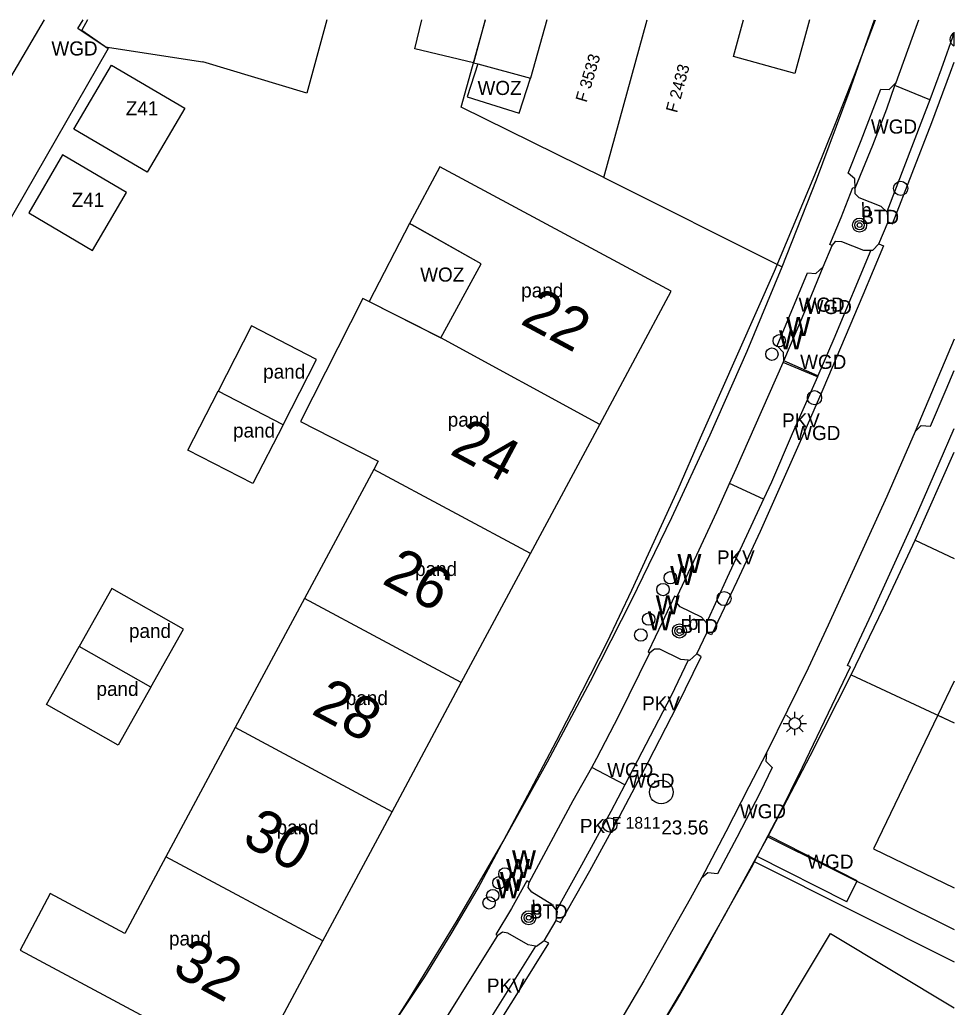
# Model space of a CAD drawing. Extents: x 198240 to 198429, y 356553 to 356721.
# Drawn here: x 198389.56 to 198429.25, y 356678.7 to 356720.63 of the extents above; entities that cross this region are included whole.
import ezdxf

# ---------------------------------------------------------------- set-up
doc = ezdxf.new("R2010")
doc.units = 0
for name, color, linetype in [('begroeid terreindeel kenmerkpunt', 7, 'Continuous'), ('bijgebouw', 7, 'Continuous'), ('BOOM', 7, 'Continuous'), ('grens individueel parkeervak', 7, 'Continuous'), ('Grens maaiveld', 7, 'Continuous'), ('grens WOZ object', 7, 'Continuous'), ('hoofdgebouw', 7, 'Continuous'), ('Hoogtepunt', 7, 'Continuous'), ('huisnummerreeks BGT', 7, 'Continuous'), ('identificerend kenmerkpunt bijpand', 7, 'Continuous'), ('identificerend kenmerkpunt pand', 7, 'Continuous'), ('identificerend kenmerkpunt parkeervak', 7, 'Continuous'), ('identificerend kenmerkpunt WOZ object', 7, 'Continuous'), ('Inspectieput_rioolput', 7, 'Continuous'), ('kant verharding', 7, 'Continuous'), ('kolk', 7, 'Continuous'), ('LICHTMAST', 7, 'Continuous'), ('Perceelnummer', 7, 'Continuous'), ('perceelsgrens_definitief', 7, 'Continuous'), ('tussenmuur', 7, 'Continuous'), ('tussenmuur bijgebouw (GBKN Zuid)', 7, 'Continuous'), ('vlakafsluiter', 7, 'Continuous'), ('waterleidingput', 7, 'Continuous'), ('wegdeel kenmerkpunt', 7, 'Continuous'), ('weginrichtingselement', 7, 'Continuous'), ('weginrichtingselement lijn', 7, 'Continuous')]:
    doc.layers.add(name, color=color, linetype=linetype)

msp = doc.modelspace()

# ---------------------------------------------------------------- linework, layer by layer
at = {"layer": 'bijgebouw'}
for p, q in [((198409.332, 356720.628), (198408.829, 356718.798)), ((198411.94, 356720.628), (198411.258, 356718.147)), ((198391.86, 356715.984), (198393.452, 356718.699)), ((198393.452, 356718.699), (198396.568, 356716.873)), ((198408.829, 356718.798), (198409.018, 356718.752)), ((198409.018, 356718.752), (198411.258, 356718.147)), ((198396.568, 356716.873), (198394.976, 356714.157)), ((198394.976, 356714.157), (198391.86, 356715.984)), ((198391.38, 356714.887), (198389.939, 356712.431)), ((198394.095, 356713.293), (198391.38, 356714.887)), ((198392.654, 356710.838), (198394.095, 356713.293)), ((198389.939, 356712.431), (198392.654, 356710.838))]:
    msp.add_line(p, q, dxfattribs=at)
for points in [[(198408.829, 356718.798), (198406.343, 356719.398), (198406.64, 356720.628)], [(198400.743, 356703.434), (198402.167, 356706.208), (198399.405, 356707.627), (198397.981, 356704.853)], [(198400.743, 356703.434), (198399.459, 356700.933), (198396.697, 356702.352), (198397.981, 356704.853)], [(198395.132, 356692.295), (198396.519, 356694.756), (198393.475, 356696.473), (198392.088, 356694.012)], [(198395.132, 356692.295), (198393.745, 356689.834), (198390.701, 356691.551), (198392.088, 356694.012)]]:
    msp.add_lwpolyline(points, dxfattribs=at)
at = {"layer": 'BOOM'}
for centre, radius in [((198425.228, 356711.909), 0.3), ((198425.228, 356711.909), 0.2), ((198425.228, 356711.909), 0.1), ((198417.58, 356694.677), 0.3), ((198417.58, 356694.677), 0.2), ((198417.58, 356694.677), 0.1), ((198411.177, 356682.499), 0.3), ((198411.177, 356682.499), 0.2), ((198411.177, 356682.499), 0.1)]:
    msp.add_circle(centre, radius, dxfattribs=at)
at = {"layer": 'grens individueel parkeervak'}
for p, q in [((198428.208, 356717.232), (198426.732, 356717.831)), ((198423.437, 356705.468), (198421.981, 356706.082)), ((198421.145, 356700.266), (198419.706, 356700.935)), ((198415.259, 356688.142), (198413.851, 356688.883))]:
    msp.add_line(p, q, dxfattribs=at)
at = {"layer": 'Grens maaiveld'}
for q in [(198422.01, 356706.149), (198423.437, 356705.468)]:
    msp.add_line((198423.457, 356705.515), q, dxfattribs=at)
for points in [[(198392.443, 356720.628), (198392.198, 356720.187), (198393.31, 356719.404), (198387.535, 356709.369)], [(198426.437, 356712.046), (198426.632, 356711.964), (198428.296, 356716.263), (198429.097, 356718.399), (198429.251, 356718.83)], [(198426.047, 356711.12), (198426.247, 356711.034), (198425.369, 356708.932), (198423.667, 356704.924), (198422.764, 356702.853), (198421.004, 356698.906), (198420.01, 356696.778), (198418.935, 356694.513), (198418.738, 356694.603)], [(198425.712, 356710.842), (198424.13, 356707.084), (198423.457, 356705.515)], [(198412.347, 356682.39), (198412.533, 356682.299), (198413.769, 356684.494), (198415.038, 356686.8), (198416.25, 356689.104), (198417.492, 356691.528), (198418.504, 356693.583), (198418.315, 356693.702)], [(198404.916, 356670.796), (198405.102, 356670.682), (198406.526, 356672.803), (198407.964, 356674.984), (198409.355, 356677.141), (198410.82, 356679.462), (198412.025, 356681.421), (198411.835, 356681.521)]]:
    msp.add_lwpolyline(points, dxfattribs=at)
at = {"layer": 'grens WOZ object'}
for p, q in [((198409.018, 356718.752), (198408.557, 356717.35)), ((198410.766, 356716.663), (198411.258, 356718.147)), ((198408.557, 356717.35), (198410.766, 356716.663)), ((198406.116, 356711.982), (198404.4, 356708.67)), ((198409.159, 356710.26), (198406.116, 356711.982)), ((198407.45, 356707.121), (198409.159, 356710.26)), ((198404.4, 356708.67), (198407.45, 356707.121))]:
    msp.add_line(p, q, dxfattribs=at)
at = {"layer": 'hoofdgebouw'}
for p, q in [((198411.253, 356697.967), (198414.193, 356703.45)), ((198404.786, 356701.891), (198404.596, 356701.537)), ((198404.596, 356701.537), (198401.654, 356696.054)), ((198408.312, 356692.484), (198411.253, 356697.967)), ((198401.654, 356696.054), (198398.712, 356690.572)), ((198429.251, 356692.542), (198428.554, 356691.097)), ((198405.372, 356687.001), (198408.312, 356692.484)), ((198398.712, 356690.572), (198395.77, 356685.089)), ((198402.431, 356681.517), (198405.372, 356687.001))]:
    msp.add_line(p, q, dxfattribs=at)
for points in [[(198423.102, 356720.628), (198422.485, 356718.353), (198419.869, 356719.062), (198420.294, 356720.628)], [(198414.193, 356703.45), (198417.228, 356709.109), (198407.402, 356714.379), (198406.116, 356711.982), (198406.233, 356711.919)], [(198407.45, 356707.121), (198409.159, 356710.26), (198406.233, 356711.919)], [(198407.45, 356707.121), (198404.136, 356708.789), (198401.488, 356703.564), (198404.786, 356701.891)], [(198428.554, 356691.097), (198425.817, 356685.422), (198429.251, 356683.766)], [(198395.77, 356685.089), (198394.02, 356681.827), (198390.856, 356683.525), (198389.57, 356681.128), (198399.396, 356675.858), (198402.431, 356681.517)], [(198420.705, 356676.348), (198423.998, 356681.827), (198429.251, 356678.669)]]:
    msp.add_lwpolyline(points, dxfattribs=at)
at = {"layer": 'Inspectieput_rioolput'}
msp.add_circle((198416.807, 356687.836), 0.5, dxfattribs=at)
at = {"layer": 'kant verharding'}
for p, q in [((198426.732, 356717.831), (198426.78, 356717.968)), ((198426.047, 356711.12), (198426.437, 356712.046)), ((198423.689, 356710.141), (198424.064, 356711.049)), ((198421.981, 356706.082), (198422.01, 356706.149)), ((198418.315, 356693.702), (198418.738, 356694.603)), ((198420.885, 356685.099), (198421.345, 356685.987)), ((198425.133, 356684.071), (198421.345, 356685.987)), ((198424.682, 356683.178), (198420.885, 356685.099)), ((198411.835, 356681.521), (198412.347, 356682.39))]:
    msp.add_line(p, q, dxfattribs=at)
for points in [[(198390.591, 356720.628), (198384.945, 356711.036)], [(198404.586, 356676.725), (198406.76, 356679.993), (198407.876, 356681.813), (198409.023, 356683.755), (198411.249, 356687.914), (198412.354, 356690.009), (198413.448, 356692.124), (198414.512, 356694.208), (198415.559, 356696.412), (198417.527, 356700.704), (198418.469, 356702.874), (198419.338, 356704.811), (198421.62, 356709.947), (198423.335, 356714.04), (198424.205, 356716.22), (198425.011, 356718.278), (198425.903, 356720.628)], [(198426.78, 356717.968), (198427.469, 356719.845), (198427.749, 356720.628)], [(198429.251, 356720.08), (198428.694, 356718.534), (198428.208, 356717.232)], [(198425.048, 356713.475), (198425.033, 356713.869), (198424.748, 356714.11), (198425.303, 356715.506), (198426.134, 356717.681), (198426.493, 356717.668), (198426.78, 356717.968)], [(198425.048, 356713.475), (198425.794, 356715.305), (198426.385, 356716.847), (198426.732, 356717.831)], [(198428.208, 356717.232), (198427.908, 356716.427), (198426.384, 356712.478)], [(198424.064, 356711.049), (198423.971, 356711.092), (198424.451, 356712.233), (198424.95, 356713.5), (198425.048, 356713.475)], [(198426.384, 356712.478), (198426.145, 356712.704), (198425.212, 356713.065), (198425.049, 356713.233), (198425.048, 356713.475)], [(198426.437, 356712.046), (198426.418, 356712.446), (198426.384, 356712.478)], [(198424.064, 356711.049), (198424.222, 356711.233), (198424.457, 356711.211), (198425.39, 356710.843), (198425.712, 356710.842)], [(198425.712, 356710.842), (198425.794, 356710.842), (198426.047, 356711.12)], [(198422.01, 356706.149), (198421.994, 356706.497), (198421.733, 356706.789), (198423.019, 356709.885), (198423.378, 356709.856), (198423.689, 356710.141)], [(198422.01, 356706.149), (198422.948, 356708.347), (198423.689, 356710.141)], [(198429.251, 356707.07), (198429.249, 356707.065), (198427.592, 356703.146)], [(198419.706, 356700.935), (198419.99, 356701.56), (198420.801, 356703.387), (198421.981, 356706.082)], [(198427.592, 356703.146), (198427.847, 356703.4), (198428.243, 356703.379), (198428.907, 356704.926), (198429.251, 356705.743)], [(198423.437, 356705.468), (198422.371, 356703.044), (198421.482, 356700.991), (198421.145, 356700.266)], [(198427.592, 356703.146), (198426.387, 356700.387), (198423.895, 356694.926), (198423.04, 356693.104), (198422.168, 356691.314), (198421.275, 356689.505)], [(198421.345, 356685.987), (198421.795, 356686.857), (198422.801, 356688.9), (198424.843, 356693.153), (198424.72, 356693.21), (198425.736, 356695.385), (198427.642, 356699.599), (198428.615, 356701.808), (198429.251, 356703.276)], [(198417.468, 356696.106), (198418.319, 356697.915), (198419.162, 356699.737), (198419.706, 356700.935)], [(198421.145, 356700.266), (198419.606, 356696.952), (198418.721, 356695.028)], [(198417.468, 356696.106), (198417.372, 356696.154), (198416.851, 356695.032), (198416.243, 356693.797), (198416.322, 356693.749)], [(198418.721, 356695.028), (198418.512, 356695.267), (198417.612, 356695.703), (198417.449, 356695.882), (198417.468, 356696.106)], [(198418.738, 356694.603), (198418.773, 356694.968), (198418.721, 356695.028)], [(198413.851, 356688.883), (198414.071, 356689.274), (198414.998, 356691.068), (198416.322, 356693.749)], [(198417.942, 356693.434), (198417.642, 356693.462), (198416.745, 356693.898), (198416.523, 356693.91), (198416.322, 356693.749)], [(198417.942, 356693.434), (198417.232, 356691.92), (198415.259, 356688.142)], [(198418.315, 356693.702), (198418.002, 356693.428), (198417.942, 356693.434)], [(198421.275, 356689.505), (198421.252, 356689.147), (198421.52, 356688.882), (198421.009, 356687.825), (198420.023, 356685.909), (198419.188, 356684.359), (198418.788, 356684.405), (198418.513, 356684.184)], [(198421.275, 356689.505), (198420.528, 356688.062), (198419.549, 356686.142), (198418.513, 356684.184)], [(198411.191, 356683.991), (198413.062, 356687.483), (198413.851, 356688.883)], [(198415.259, 356688.142), (198414.67, 356687.011), (198413.423, 356684.735), (198412.352, 356682.826)], [(198393.74, 356645.683), (198394.852, 356647.053), (198396.077, 356648.617), (198397.345, 356650.191), (198399.817, 356653.369), (198401.05, 356654.94), (198403.957, 356658.838), (198407.667, 356663.939), (198410.624, 356668.271), (198412.002, 356670.335), (198414.253, 356673.784), (198415.317, 356675.477), (198416.394, 356677.211), (198417.49, 356679.043), (198418.49, 356680.762), (198419.487, 356682.592), (198420.694, 356684.729), (198420.885, 356685.099)], [(198418.513, 356684.184), (198418.032, 356683.303), (198416.065, 356679.815), (198415.042, 356678.098), (198413.982, 356676.397), (198412.924, 356674.725), (198411.836, 356673.035), (198410.73, 356671.365), (198409.617, 356669.703)], [(198411.191, 356683.991), (198411.102, 356684.062), (198410.446, 356682.888), (198409.778, 356681.793), (198409.862, 356681.744)], [(198412.352, 356682.826), (198412.165, 356683.067), (198411.302, 356683.587), (198411.157, 356683.784), (198411.191, 356683.991)], [(198412.347, 356682.39), (198412.402, 356682.762), (198412.352, 356682.826)], [(198406.901, 356677.03), (198407.203, 356677.485), (198409.346, 356680.906), (198409.862, 356681.744)], [(198411.465, 356681.29), (198411.159, 356681.348), (198410.29, 356681.85), (198410.056, 356681.895), (198409.862, 356681.744)], [(198411.465, 356681.29), (198408.989, 356677.334), (198408.215, 356676.157)], [(198411.835, 356681.521), (198411.512, 356681.281), (198411.465, 356681.29)]]:
    msp.add_lwpolyline(points, dxfattribs=at)
at = {"layer": 'kolk'}
msp.add_line((198429.251, 356719.514), (198429.251, 356720.07), dxfattribs=at)
for centre in [(198426.977, 356713.469), (198423.315, 356704.58), (198419.474, 356696.053), (198414.625, 356686.439)]:
    msp.add_circle(centre, 0.3, dxfattribs=at)
msp.add_arc((198429.365, 356719.792), 0.3, 112.3125, 247.6875, dxfattribs=at)
at = {"layer": 'LICHTMAST'}
for p, q in [((198422.482, 356690.998), (198422.482, 356691.248)), ((198422.305, 356690.925), (198422.128, 356691.102)), ((198422.659, 356690.925), (198422.836, 356691.102)), ((198421.982, 356690.748), (198422.232, 356690.748)), ((198422.128, 356690.394), (198422.305, 356690.571)), ((198422.482, 356690.248), (198422.482, 356690.498)), ((198422.836, 356690.394), (198422.659, 356690.571)), ((198422.732, 356690.748), (198422.982, 356690.748))]:
    msp.add_line(p, q, dxfattribs=at)
msp.add_circle((198422.482, 356690.748), 0.25, dxfattribs=at)
at = {"layer": 'perceelsgrens_definitief'}
for points in [[(198392.026, 356720.255), (198392.248, 356720.628)], [(198402.603, 356720.628), (198401.758, 356717.506), (198397.339, 356718.835)], [(198414.372, 356713.928), (198408.309, 356716.912), (198409.334, 356720.628)], [(198414.372, 356713.928), (198416.203, 356720.628)], [(198421.942, 356710.139), (198423.4, 356713.831), (198424.785, 356717.551), (198425.864, 356720.628)], [(198393.187, 356719.473), (198392.026, 356720.255)], [(198393.187, 356719.473), (198397.339, 356718.835)], [(198414.372, 356713.928), (198421.942, 356710.139)], [(198392.722, 356660.05), (198395.103, 356663.112), (198397.425, 356666.219), (198399.689, 356669.369), (198401.891, 356672.562), (198404.033, 356675.796), (198406.114, 356679.07), (198408.131, 356682.383), (198410.086, 356685.733), (198411.977, 356689.12), (198413.803, 356692.543), (198415.563, 356695.999), (198417.258, 356699.488), (198418.887, 356703.008), (198420.448, 356706.559), (198421.942, 356710.139)], [(198427.584, 356698.531), (198429.251, 356702.262)], [(198424.868, 356692.818), (198426.247, 356695.665), (198427.584, 356698.531)], [(198427.584, 356698.531), (198429.251, 356697.749)], [(198421.33, 356685.94), (198421.343, 356685.963), (198423.135, 356689.375), (198424.868, 356692.818)], [(198424.868, 356692.818), (198429.251, 356690.772)], [(198420.752, 356684.884), (198421.33, 356685.94)], [(198421.33, 356685.94), (198429.251, 356682)], [(198415.612, 356675.921), (198417.581, 356679.235), (198419.491, 356682.582), (198420.752, 356684.884)], [(198420.752, 356684.884), (198429.251, 356680.633)]]:
    msp.add_lwpolyline(points, dxfattribs=at)
at = {"layer": 'tussenmuur'}
for p, q in [((198414.193, 356703.45), (198407.45, 356707.121)), ((198411.253, 356697.967), (198404.596, 356701.537)), ((198408.312, 356692.484), (198401.654, 356696.054)), ((198428.554, 356691.097), (198429.251, 356690.77)), ((198405.372, 356687.001), (198398.712, 356690.572)), ((198402.431, 356681.517), (198395.77, 356685.089))]:
    msp.add_line(p, q, dxfattribs=at)
at = {"layer": 'tussenmuur bijgebouw (GBKN Zuid)'}
for p, q in [((198400.743, 356703.434), (198397.981, 356704.853)), ((198395.132, 356692.295), (198392.088, 356694.012))]:
    msp.add_line(p, q, dxfattribs=at)
at = {"layer": 'vlakafsluiter'}
msp.add_line((198424.682, 356683.178), (198425.133, 356684.071), dxfattribs=at)
at = {"layer": 'waterleidingput'}
for centre in [(198421.816, 356707), (198421.816, 356707), (198421.508, 356706.43), (198421.508, 356706.43), (198417.19, 356696.936), (198417.19, 356696.936), (198416.881, 356696.436), (198416.881, 356696.436), (198416.271, 356695.18), (198416.271, 356695.18), (198415.938, 356694.504), (198415.938, 356694.504), (198410.164, 356684.357), (198410.164, 356684.357), (198409.913, 356683.985), (198409.913, 356683.985), (198409.649, 356683.443), (198409.649, 356683.443), (198409.493, 356683.132), (198409.493, 356683.132)]:
    msp.add_circle(centre, 0.263, dxfattribs=at)
at = {"layer": 'weginrichtingselement lijn'}
for points in [[(198426.437, 356712.046), (198426.632, 356711.964), (198428.296, 356716.263), (198429.097, 356718.399), (198429.251, 356718.83)], [(198426.047, 356711.12), (198426.247, 356711.034), (198425.369, 356708.932), (198423.667, 356704.924), (198422.764, 356702.853), (198421.004, 356698.906), (198420.01, 356696.778), (198418.935, 356694.513), (198418.738, 356694.603)], [(198412.347, 356682.39), (198412.533, 356682.299), (198413.769, 356684.494), (198415.038, 356686.8), (198416.25, 356689.104), (198417.492, 356691.528), (198418.504, 356693.583), (198418.315, 356693.702)], [(198404.916, 356670.796), (198405.102, 356670.682), (198406.526, 356672.803), (198407.964, 356674.984), (198409.355, 356677.141), (198410.82, 356679.462), (198412.025, 356681.421), (198411.835, 356681.521)]]:
    msp.add_lwpolyline(points, dxfattribs=at)

# ---------------------------------------------------------------- texts
at = {"layer": 'begroeid terreindeel kenmerkpunt'}
for p in [(198425.303, 356711.958), (198417.619, 356694.585), (198411.223, 356682.468)]:
    msp.add_text('BTD', height=0.6, dxfattribs=at).set_placement(p)
at = {"layer": 'Hoogtepunt'}
msp.add_text('23.56', height=0.6, dxfattribs=at).set_placement((198416.807, 356686.036))
msp.add_text('23.56', height=0.6, dxfattribs=at).set_placement((198416.807, 356686.036))
at = {"layer": 'huisnummerreeks BGT'}
for s, p in [('22', (198410.772, 356707.742)), ('24', (198407.772, 356702.211)), ('26', (198404.892, 356696.715)), ('28', (198401.891, 356691.182)), ('30', (198398.938, 356685.663)), ('32', (198395.971, 356680.143))]:
    msp.add_text(s, height=1.8, rotation=331.8, dxfattribs=at).set_placement(p)
at = {"layer": 'identificerend kenmerkpunt bijpand'}
for s, p in [('Z41', (198394.061, 356716.568)), ('Z41', (198391.763, 356712.685)), ('pand', (198399.898, 356705.39)), ('pand', (198398.618, 356702.89)), ('pand', (198394.198, 356694.38)), ('pand', (198392.818, 356691.92))]:
    msp.add_text(s, height=0.6, dxfattribs=at).set_placement(p)
at = {"layer": 'identificerend kenmerkpunt pand'}
for p in [(198410.858, 356708.84), (198407.738, 356703.35), (198406.348, 356697.01), (198403.408, 356691.53), (198400.468, 356686.04), (198395.898, 356681.32)]:
    msp.add_text('pand', height=0.6, dxfattribs=at).set_placement(p)
at = {"layer": 'identificerend kenmerkpunt parkeervak'}
for p in [(198421.938, 356703.317), (198419.172, 356697.5), (198415.996, 356691.301), (198413.352, 356686.099), (198409.402, 356679.321)]:
    msp.add_text('PKV', height=0.6, dxfattribs=at).set_placement(p)
at = {"layer": 'identificerend kenmerkpunt WOZ object'}
for p in [(198409.002, 356717.434), (198406.567, 356709.509)]:
    msp.add_text('WOZ', height=0.6, dxfattribs=at).set_placement(p)
at = {"layer": 'Perceelnummer'}
for s, rotation, p in [('F 3533', 73.4, (198413.631, 356717.091)), ('F 2433', 74.9, (198417.474, 356716.65))]:
    msp.add_text(s, height=0.5, rotation=rotation, dxfattribs=at).set_placement(p)
msp.add_text('F 1811', height=0.5, dxfattribs=at).set_placement((198414.696, 356686.282))
at = {"layer": 'waterleidingput'}
for p in [(198422.12, 356707.198), (198421.812, 356706.628), (198417.494, 356697.134), (198417.185, 356696.634), (198416.575, 356695.378), (198416.242, 356694.702), (198410.468, 356684.555), (198410.217, 356684.183), (198409.797, 356683.33), (198409.953, 356683.641)]:
    msp.add_text('w', height=1.05, dxfattribs=at).set_placement(p)
at = {"layer": 'wegdeel kenmerkpunt'}
for p in [(198390.903, 356719.11), (198425.71, 356715.794), (198422.636, 356708.231), (198422.939, 356708.131), (198422.705, 356705.804), (198422.455, 356702.783), (198414.506, 356688.475), (198415.406, 356688.023), (198420.144, 356686.723), (198423.011, 356684.584)]:
    msp.add_text('WGD', height=0.6, dxfattribs=at).set_placement(p)
at = {"layer": 'weginrichtingselement'}
for p in [(198425.288, 356712.251), (198417.939, 356694.726), (198411.3, 356682.632)]:
    msp.add_text('b', height=0.6, rotation=0.2905, dxfattribs=at).set_placement(p)

doc.saveas('drawing.dxf')
